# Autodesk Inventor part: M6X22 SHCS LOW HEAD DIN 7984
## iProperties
Created: 2006-02
Part Number: M6X22 SHCS LOW HEAD DIN 7984
Material: Steel, Mild
Description: Cylinder Head Cap Screw
Document SubType Name: Modeling
Standard: DIN 7984
Designer: Andy Moles
Standards Organization: DIN
Language: en-US
Size Designation: M6 x 20
Categories: <MemberInstance><Categories><Category DisplayName="Fasteners" InternalName="e4da775c-781d-43d5-af7c-5136215cf5a6" Mnemonic="FSTN"><Category DisplayName="Bolts"
Density: 7.86 g/cm^3
Author: Andy Moles
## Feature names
1. Body [Revolution]
2. Slot [Extrusion]
3. Fillet1
4. Chamfer1
